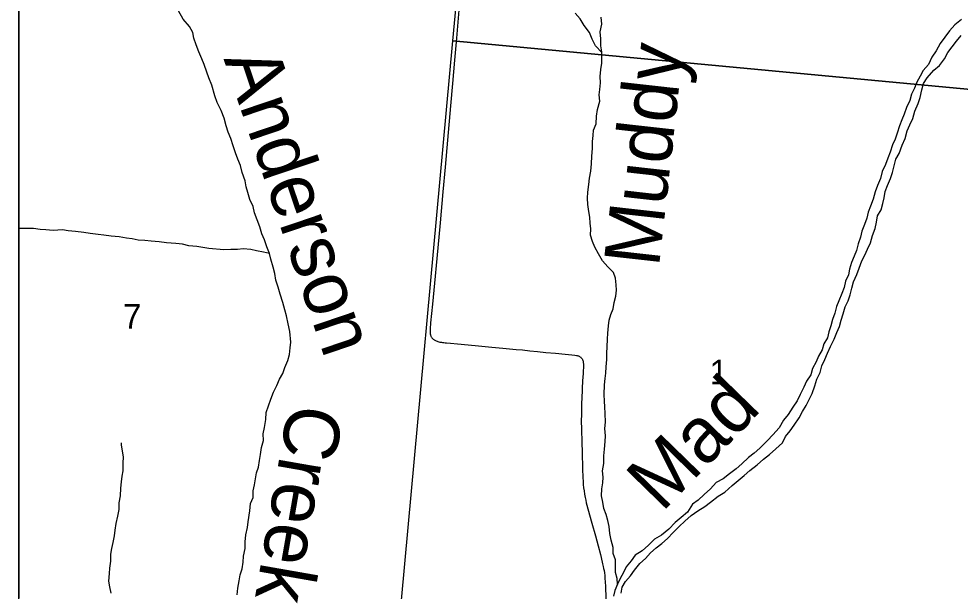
# Model space of a CAD drawing. Extents: x 0 to 1067, y 0 to 440.
# Drawn here: x 131 to 227.4, y 201.4 to 260 of the extents above; entities that cross this region are included whole.
import ezdxf

# ---------------------------------------------------------------- set-up
doc = ezdxf.new("R2010")
doc.units = 0
for name, color, linetype in [('GM_X_Major_River', 7, 'Continuous'), ('GM_X_Major_River_Text', 7, 'Continuous'), ('GM_X_Minor_River', 7, 'Continuous'), ('GM_X_Minor_River_Text', 7, 'Continuous'), ('GM_X_Section', 7, 'Continuous'), ('GM_X_Section_Text', 7, 'Continuous'), ('GM_X_Township_Road', 7, 'Continuous'), ('SH_Text', 7, 'Continuous')]:
    doc.layers.add(name, color=color, linetype=linetype)

msp = doc.modelspace()

# ---------------------------------------------------------------- linework, layer by layer
at = {"layer": 'GM_X_Major_River'}
for points in [[(227.541, 259.901), (226.865, 259.35), (226.301, 258.751), (225.352, 257.454), (224.966, 256.689), (224.514, 256.04), (224.152, 255.32), (223.632, 254.695), (223.297, 254.112), (222.982, 253.481), (222.737, 252.895), (222.423, 252.265), (222.244, 251.607), (221.928, 250.909), (221.68, 250.231), (221.436, 249.644), (221.189, 249.012), (220.963, 248.287), (220.74, 247.655), (220.473, 247.068), (220.223, 246.322), (220, 245.712), (219.777, 245.079), (219.436, 244.335), (219.234, 243.633), (218.939, 242.911), (218.693, 242.256), (218.512, 241.53), (218.218, 240.808), (217.972, 240.198), (217.84, 239.585), (217.616, 238.93), (217.323, 238.253)], [(218.221, 237.038), (218.425, 237.786), (218.697, 238.509), (218.83, 239.167), (218.94, 239.804), (219.322, 240.432), (219.5, 241.066), (219.609, 241.657), (219.719, 242.316), (219.964, 242.926), (220.259, 243.648), (220.481, 244.258), (220.637, 244.916), (220.817, 245.596), (221.153, 246.203), (221.474, 247.061), (221.767, 247.738), (221.994, 248.508), (222.24, 249.117), (222.578, 249.77), (222.782, 250.54), (223.124, 251.307), (223.324, 251.94), (223.483, 252.712), (223.661, 253.347), (224.02, 253.953), (224.703, 254.709), (225.286, 255.194), (225.807, 255.887), (226.145, 256.516), (226.594, 257.097), (227.022, 257.701), (227.517, 258.28)], [(217.323, 238.253), (217.191, 237.617), (216.966, 236.939), (216.787, 236.259), (216.542, 235.672), (216.295, 235.017), (216.071, 234.338), (215.986, 233.77), (215.671, 233.116), (215.515, 232.459), (215.293, 231.871), (214.974, 231.104), (214.752, 230.517), (214.574, 229.86), (214.327, 229.205), (214.148, 228.547), (213.948, 227.936), (213.817, 227.324), (213.457, 226.717), (213.28, 226.106), (212.897, 225.455), (212.652, 224.868), (212.29, 224.171), (212.112, 223.537), (211.661, 222.888), (211.392, 222.279), (211.029, 221.536), (210.714, 220.883), (210.263, 220.234), (209.808, 219.471), (209.313, 218.892), (208.857, 218.106), (208.222, 217.394), (207.681, 216.816), (206.884, 216.018), (206.3, 215.51), (205.718, 215.071), (205.061, 214.406), (204.454, 213.899), (203.779, 213.394), (203.127, 212.888), (202.432, 212.498), (201.845, 211.876), (201.19, 211.279), (200.581, 210.704), (200, 210.287), (199.475, 209.481), (198.822, 208.929), (198.214, 208.4), (197.58, 207.733), (196.811, 207.117), (196.093, 206.705), (195.506, 206.106), (194.829, 205.533), (194.133, 205.075), (193.706, 204.493), (193.21, 203.869), (192.919, 203.284), (192.583, 202.677), (192.315, 202.091), (192.047, 201.46), (191.915, 200.87)], [(192.676, 201.189), (192.784, 201.78), (193.143, 202.363), (193.639, 202.965), (194.065, 203.546), (194.609, 204.215), (195.193, 204.745), (195.688, 205.324), (196.272, 205.831), (196.854, 206.271), (197.439, 206.778), (198.003, 207.401), (198.636, 208.021), (199.221, 208.552), (199.852, 209.126), (200.549, 209.608), (201.245, 210.043), (201.85, 210.505), (202.619, 211.098), (203.292, 211.535), (204.063, 212.22), (204.669, 212.704), (205.276, 213.211), (205.861, 213.742), (206.63, 214.335), (207.26, 214.887), (207.867, 215.371), (208.521, 215.946), (209.199, 216.565), (209.514, 217.218), (210.009, 217.797), (210.413, 218.379), (210.913, 219.118), (211.274, 219.792), (211.634, 220.398), (212.261, 221.613), (212.535, 222.404), (212.737, 223.106), (213.076, 223.782), (213.232, 224.462), (213.547, 225.115), (213.816, 225.747), (214.132, 226.423), (214.519, 227.188), (214.766, 227.866), (215.035, 228.498), (215.236, 229.131), (215.437, 229.788), (215.639, 230.49), (215.931, 231.121), (216.131, 231.732), (216.31, 232.412), (216.488, 233.046), (216.829, 233.813), (217.053, 234.446), (217.348, 235.191), (217.661, 235.775), (217.93, 236.407), (218.221, 237.038)]]:
    msp.add_lwpolyline(points, dxfattribs=at)
at = {"layer": 'GM_X_Minor_River'}
for points in [[(154.646, 241.471), (154.439, 242.186), (154.275, 242.785), (154.179, 243.405), (153.884, 244.236), (153.7, 244.95), (153.447, 245.62), (153.192, 246.267), (152.94, 246.983), (152.711, 247.721), (152.435, 248.392), (152.225, 249.015), (152.021, 249.821), (151.725, 250.584), (151.316, 251.419), (151.063, 252.112), (150.753, 253.172), (150.456, 253.935), (150.246, 254.535), (149.973, 255.32), (149.739, 255.898), (149.419, 256.616), (149.167, 257.332), (148.913, 258.002), (148.816, 258.576), (148.469, 259.181), (147.832, 259.954), (147.356, 260.814)], [(190.698, 256.545), (190.054, 257.197), (189.71, 257.893), (189.457, 258.563), (188.909, 259.288), (188.496, 259.963), (187.967, 260.55)], [(192.317, 202.094), (192.265, 202.687), (192.101, 203.309), (192.12, 203.971), (192.116, 204.611), (191.884, 205.258), (191.879, 205.852), (191.673, 206.612), (191.534, 207.302), (191.463, 207.99), (191.323, 208.634), (191.158, 209.233), (190.926, 209.857), (190.808, 210.5), (190.667, 211.144), (190.711, 211.851), (190.798, 212.488), (190.86, 213.057), (190.788, 213.722), (190.9, 214.45), (190.923, 215.226), (190.966, 215.91), (191.057, 216.707), (191.097, 217.277), (191.029, 218.056), (191.069, 218.671), (191.05, 219.586), (191.025, 220.272), (190.996, 220.844), (190.948, 221.531), (190.999, 222.512), (191.063, 223.15), (191.103, 223.72), (191.167, 224.357), (191.212, 225.11), (191.208, 225.75), (191.25, 226.411), (191.295, 227.186), (191.336, 227.802), (191.381, 228.555), (191.466, 229.123), (191.642, 229.712), (191.887, 230.298), (191.974, 230.935), (192.129, 231.57), (192.215, 232.184), (192.186, 232.756), (192.115, 233.421), (191.904, 233.999), (191.329, 234.588), (190.778, 235.198), (190.366, 235.919), (189.999, 236.593), (189.766, 237.194), (189.557, 237.817), (189.576, 238.479), (189.502, 239.076), (189.474, 239.671), (189.378, 240.267), (189.261, 240.956), (189.235, 241.62), (189.276, 242.235), (189.39, 243.031), (189.431, 243.67), (189.589, 244.373), (189.656, 245.125), (189.702, 245.923), (189.748, 246.698), (189.746, 247.407), (189.832, 248.021), (189.871, 248.591), (190.14, 249.222), (190.163, 249.998), (190.252, 250.703), (190.504, 251.541), (190.431, 252.183), (190.494, 252.752), (190.559, 253.435), (190.555, 254.075), (190.622, 254.804), (190.709, 255.441), (190.703, 256.035), (190.697, 256.606), (190.624, 257.225), (190.622, 257.933), (190.552, 258.644), (190.712, 259.438), (190.641, 260.149)], [(153.374, 201.004), (153.416, 201.688), (153.576, 202.46), (153.685, 203.074), (153.862, 203.686), (153.973, 204.367), (154.014, 204.983), (154.173, 205.755), (154.193, 206.44), (154.259, 207.146), (154.418, 207.918), (154.48, 208.487), (154.649, 209.602), (154.74, 210.376), (154.985, 210.962), (155.005, 211.647), (155.137, 212.26), (155.223, 212.874), (155.332, 213.487), (155.531, 214.075), (155.643, 214.78), (155.752, 215.394), (155.863, 216.099), (156.043, 216.801), (156.019, 217.51), (156.174, 218.145), (156.312, 218.964), (156.333, 219.694), (156.58, 220.349), (156.805, 221.05), (157.099, 221.75), (157.438, 222.447), (157.685, 223.102), (158.043, 223.685), (158.242, 224.273), (158.537, 224.995), (158.737, 225.629), (158.779, 226.29), (158.842, 226.882), (158.76, 227.958), (158.6, 228.74), (158.42, 229.568), (158.233, 230.19), (158.028, 230.951), (157.778, 231.781), (157.572, 232.495), (157.32, 233.234), (157.203, 233.9), (157.063, 234.567), (156.813, 235.374), (156.671, 235.95), (156.395, 236.643), (156.165, 237.359), (155.888, 237.984), (155.68, 238.676), (155.405, 239.392), (155.153, 240.131), (154.99, 240.775), (154.646, 241.471)], [(156.671, 235.95), (156.061, 236.105), (155.358, 236.218), (154.747, 236.351), (153.976, 236.443), (153.382, 236.37), (152.698, 236.368), (151.992, 236.344), (150.448, 236.483), (149.246, 236.656), (148.406, 236.751), (147.751, 236.908), (147.07, 236.974), (146.115, 237.049), (145.39, 237.163), (144.549, 237.211), (143.914, 237.299), (143.232, 237.32), (142.621, 237.453), (142.031, 237.516), (141.283, 237.653), (140.466, 237.724), (139.718, 237.838), (139.128, 237.902), (138.311, 237.995), (137.654, 238.106), (136.814, 238.2), (136.065, 238.292), (135.476, 238.378), (134.518, 238.316), (133.768, 238.384), (133.177, 238.402), (132.497, 238.514), (131.859, 238.511), (131.2, 238.531), (131, 238.529)], [(140.447, 201.193), (140.329, 201.836), (140.232, 202.41), (140.3, 203.185), (140.317, 203.756), (140.406, 204.461), (140.426, 205.169), (140.512, 205.76), (140.666, 206.373), (140.8, 207.054), (140.863, 207.646), (140.974, 208.328), (141.132, 209.055), (141.265, 209.736), (141.263, 210.421), (141.398, 211.148), (141.443, 211.924), (141.531, 212.584), (141.593, 213.153), (141.678, 213.722), (141.678, 214.521), (141.718, 215.114), (141.623, 215.757), (141.526, 216.331), (141.51, 216.56)]]:
    msp.add_lwpolyline(points, dxfattribs=at)
at = {"layer": 'GM_X_Section'}
for points in [[(180.984, 316.33), (240.782, 310.986), (235.406, 252.097), (175.453, 257.739)], [(175.453, 257.739), (235.406, 252.097), (230.143, 191.616), (169.87, 197.127)]]:
    msp.add_lwpolyline(points, close=True, dxfattribs=at)
at = {"layer": 'GM_X_Township_Road'}
for points in [[(131, 425.107), (131, 200.68)], [(176.075, 260.863), (175.816, 258.008), (175.629, 255.747), (175.432, 253.373), (175.214, 251.079), (174.918, 247.557), (174.652, 244.805), (174.415, 242.255), (174.14, 239.098), (173.796, 235.426), (173.564, 232.904), (173.362, 230.756), (173.168, 228.85), (173.123, 228.243), (173.118, 228.1), (173.122, 227.939), (173.127, 227.861), (173.133, 227.775), (173.144, 227.703), (173.157, 227.646), (173.171, 227.589), (173.189, 227.54), (173.213, 227.488), (173.243, 227.432), (173.271, 227.38), (173.314, 227.323), (173.349, 227.279), (173.383, 227.242), (173.43, 227.197), (173.494, 227.146), (173.544, 227.111), (173.611, 227.069), (173.674, 227.037), (173.751, 227), (173.842, 226.966), (173.928, 226.938), (174.011, 226.911), (174.106, 226.894), (174.192, 226.877), (174.296, 226.862), (174.399, 226.85), (174.52, 226.835), (174.663, 226.822), (174.806, 226.81), (175.216, 226.778), (175.925, 226.719), (177.72, 226.541), (179.446, 226.379), (180.576, 226.275), (181.947, 226.137), (182.572, 226.079), (183.346, 225.997), (184.137, 225.915), (184.985, 225.831), (185.971, 225.742), (186.943, 225.654), (187.64, 225.584), (187.93, 225.551), (188.114, 225.52), (188.183, 225.506), (188.246, 225.491), (188.308, 225.471), (188.373, 225.444), (188.426, 225.419), (188.479, 225.387), (188.515, 225.365), (188.574, 225.321), (188.609, 225.289), (188.641, 225.254), (188.673, 225.21), (188.695, 225.17), (188.72, 225.119), (188.742, 225.067), (188.762, 225.015), (188.781, 224.956), (188.796, 224.896), (188.806, 224.825), (188.811, 224.763), (188.816, 224.687), (188.818, 224.529), (188.816, 224.302), (188.797, 223.901), (188.783, 223.613), (188.764, 223.356), (188.735, 222.844), (188.706, 222.186), (188.694, 221.819), (188.674, 221.304), (188.644, 220.458), (188.629, 219.905), (188.616, 219.427), (188.61, 218.873), (188.614, 217.945), (188.647, 216.642), (188.686, 215.599), (188.734, 213.959), (188.768, 212.99), (188.79, 212.657), (188.813, 212.321), (188.849, 211.967), (188.885, 211.654), (188.938, 211.306), (188.994, 210.992), (189.056, 210.709), (189.116, 210.446), (189.698, 208.347), (190.058, 207.055), (190.329, 206.014), (190.571, 205.131), (190.753, 204.362), (190.79, 204.197), (190.857, 203.908), (190.896, 203.701), (190.936, 203.493), (190.97, 203.267), (191, 202.981), (191.019, 202.675), (191.044, 202.335), (191.074, 201.866), (191.089, 201.575), (191.162, 200.258)]]:
    msp.add_lwpolyline(points, dxfattribs=at)
at = {"layer": 'SH_Text'}
msp.add_lwpolyline([(131, 425.107), (539, 425.107), (539, 17.107), (131, 17.107)], close=True, dxfattribs=at)

# ---------------------------------------------------------------- texts
at = {"layer": 'GM_X_Major_River_Text'}
msp.add_text('Mad', height=5.6789, rotation=45.77833, dxfattribs=at).set_placement((196.857, 209.382))
at = {"layer": 'GM_X_Minor_River_Text'}
for s, height, rotation, p in [('Muddy', 5.6787, 83.61679, (196.554, 234.478)), ('Anderson', 5.6804, 288.67579, (151.957, 255.89)), ('Creek', 5.6788, 260.08523, (158.681, 220.756))]:
    msp.add_text(s, height=height, rotation=rotation, dxfattribs=at).set_placement(p)
at = {"layer": 'GM_X_Section_Text'}
for s, p in [('7', (141.679, 228.257)), ('1', (201.754, 222.576))]:
    msp.add_text(s, height=2.511, rotation=0.00001, dxfattribs=at).set_placement(p)

doc.saveas('drawing.dxf')
